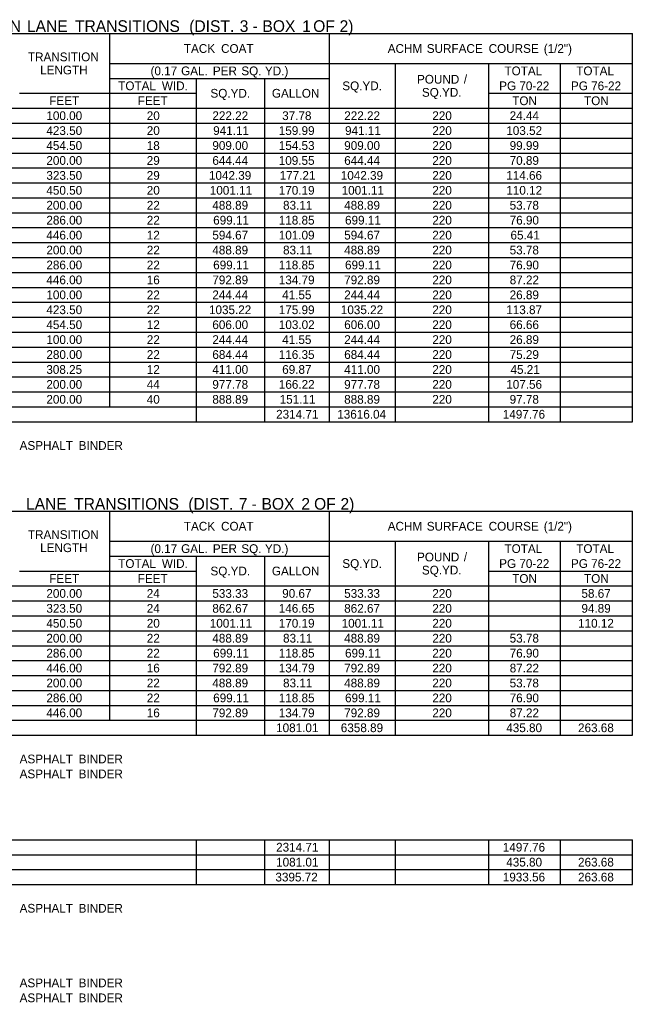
# Model space of a CAD drawing. Extents: x 544478 to 1930787, y -1948294 to 596640.
# Drawn here: x 548715 to 549135, y -1946843 to -1946169 of the extents above; entities that cross this region are included whole.
import ezdxf

# ---------------------------------------------------------------- set-up
doc = ezdxf.new("R2010")
doc.units = 0
doc.layers.add('Default', color=7, linetype='Continuous')

msp = doc.modelspace()

# ---------------------------------------------------------------- linework, layer by layer
at = {"layer": 'Default'}
for p, q in [((548361.91, -1946178.84), (549135.09, -1946178.84)), ((548361.91, -1946178.84), (549135.09, -1946178.84)), ((548776.78, -1946434.78), (548776.78, -1946178.84)), ((548927.41, -1946199.32), (548927.41, -1946178.84)), ((548927.41, -1946445.02), (548927.41, -1946178.84)), ((549135.09, -1946445.02), (549135.09, -1946178.84)), ((548776.78, -1946199.32), (549135.09, -1946199.32)), ((548927.41, -1946199.32), (549036.61, -1946199.32)), ((548972.75, -1946445.02), (548972.75, -1946199.32)), ((549036.61, -1946445.02), (549036.61, -1946199.32)), ((549085.85, -1946445.02), (549085.85, -1946199.32)), ((548776.78, -1946209.55), (548927.41, -1946209.55)), ((548836.25, -1946445.02), (548836.25, -1946209.55)), ((548883.05, -1946445.02), (548883.05, -1946209.55)), ((548714.86, -1946219.79), (548776.78, -1946219.79)), ((548714.86, -1946219.79), (548836.25, -1946219.79)), ((548836.25, -1946230.03), (548836.25, -1946219.79)), ((549036.61, -1946219.79), (549135.09, -1946219.79)), ((548361.91, -1946230.03), (549135.09, -1946230.03)), ((548836.25, -1946230.03), (548883.05, -1946230.03)), ((548883.05, -1946230.03), (549135.09, -1946230.03)), ((548577.88, -1946240.27), (549135.09, -1946240.27)), ((548577.88, -1946250.5), (549135.09, -1946250.5)), ((548361.91, -1946260.74), (549135.09, -1946260.74)), ((548577.88, -1946270.98), (549135.09, -1946270.98)), ((548577.88, -1946281.22), (549135.09, -1946281.22)), ((548361.91, -1946291.45), (549036.61, -1946291.45)), ((548714.86, -1946291.45), (548836.25, -1946291.45)), ((548836.25, -1946291.45), (549135.09, -1946291.45)), ((549036.61, -1946291.45), (549085.85, -1946291.45)), ((548577.88, -1946301.69), (549135.09, -1946301.69)), ((548577.88, -1946311.93), (549135.09, -1946311.93)), ((548361.91, -1946322.17), (549135.09, -1946322.17)), ((548577.88, -1946332.4), (549135.09, -1946332.4)), ((548577.88, -1946342.64), (549135.09, -1946342.64)), ((548361.91, -1946352.88), (549036.61, -1946352.88)), ((548714.86, -1946352.88), (548836.25, -1946352.88)), ((548836.25, -1946352.88), (549135.09, -1946352.88)), ((548577.88, -1946363.12), (549135.09, -1946363.12)), ((548577.88, -1946373.35), (549135.09, -1946373.35)), ((548361.91, -1946383.59), (549135.09, -1946383.59)), ((548577.88, -1946393.83), (549135.09, -1946393.83)), ((548577.88, -1946404.07), (549135.09, -1946404.07)), ((548361.91, -1946414.3), (549135.09, -1946414.3)), ((548577.88, -1946414.3), (549135.09, -1946414.3)), ((548524.25, -1946424.54), (549135.09, -1946424.54)), ((549036.61, -1946424.54), (549135.09, -1946424.54)), ((548361.91, -1946434.78), (549135.09, -1946434.78)), ((549036.61, -1946434.78), (549085.85, -1946434.78)), ((549085.85, -1946434.78), (549135.09, -1946434.78)), ((548361.91, -1946445.02), (549135.09, -1946445.02)), ((548361.91, -1946506.44), (549135.09, -1946506.44)), ((548361.91, -1946506.44), (549135.09, -1946506.44)), ((548776.78, -1946649.77), (548776.78, -1946506.44)), ((548927.41, -1946526.92), (548927.41, -1946506.44)), ((548927.41, -1946660), (548927.41, -1946506.44)), ((549135.09, -1946660), (549135.09, -1946506.44)), ((548776.78, -1946526.92), (549135.09, -1946526.92)), ((548927.41, -1946526.92), (549036.61, -1946526.92)), ((548972.75, -1946660), (548972.75, -1946526.92)), ((549036.61, -1946660), (549036.61, -1946526.92)), ((549085.85, -1946660), (549085.85, -1946526.92)), ((548776.78, -1946537.15), (548927.41, -1946537.15)), ((548836.25, -1946660), (548836.25, -1946537.15)), ((548883.05, -1946660), (548883.05, -1946537.15)), ((548714.86, -1946547.39), (548776.78, -1946547.39)), ((548714.86, -1946547.39), (548836.25, -1946547.39)), ((548836.25, -1946557.63), (548836.25, -1946547.39)), ((549036.61, -1946547.39), (549135.09, -1946547.39)), ((548361.91, -1946557.63), (549135.09, -1946557.63)), ((548836.25, -1946557.63), (548883.05, -1946557.63)), ((548883.05, -1946557.63), (549135.09, -1946557.63)), ((548577.88, -1946567.87), (549135.09, -1946567.87)), ((548577.88, -1946578.1), (548836.25, -1946578.1)), ((548577.88, -1946578.1), (548776.78, -1946578.1)), ((548776.78, -1946578.1), (549135.09, -1946578.1)), ((548361.91, -1946588.34), (549135.09, -1946588.34)), ((548577.88, -1946598.58), (549135.09, -1946598.58)), ((548577.88, -1946608.82), (548836.25, -1946608.82)), ((548577.88, -1946608.82), (548776.78, -1946608.82)), ((548776.78, -1946608.82), (549135.09, -1946608.82)), ((548361.91, -1946619.05), (549135.09, -1946619.05)), ((548577.88, -1946629.29), (549135.09, -1946629.29)), ((548577.88, -1946639.53), (548836.25, -1946639.53)), ((548577.88, -1946639.53), (548776.78, -1946639.53)), ((548776.78, -1946639.53), (549135.09, -1946639.53)), ((548361.91, -1946649.77), (549135.09, -1946649.77)), ((548361.91, -1946660), (549135.09, -1946660)), ((548361.91, -1946731.67), (549135.09, -1946731.67)), ((548361.91, -1946731.67), (549135.09, -1946731.67)), ((548836.25, -1946762.38), (548836.25, -1946731.67)), ((548883.05, -1946762.38), (548883.05, -1946731.67)), ((548927.41, -1946762.38), (548927.41, -1946731.67)), ((548972.75, -1946762.38), (548972.75, -1946731.67)), ((549036.61, -1946762.38), (549036.61, -1946731.67)), ((549085.85, -1946762.38), (549085.85, -1946731.67)), ((549135.09, -1946762.38), (549135.09, -1946731.67)), ((548361.91, -1946741.9), (549135.09, -1946741.9)), ((548361.91, -1946752.14), (549135.09, -1946752.14)), ((548361.91, -1946762.38), (549135.09, -1946762.38))]:
    msp.add_line(p, q, dxfattribs=at)

# ---------------------------------------------------------------- texts
for s, height, p in [(' MAIN', 8, (548686.12, -1946177.72)), (' LANE', 8, (548716.88, -1946177.72)), (' TRANSITIONS', 8, (548749.87, -1946177.72)), (' (DIST.', 8, (548828.19, -1946177.72)), (' 3', 8, (548862.81, -1946177.72)), (' -', 8, (548871.65, -1946177.72)), (' BOX', 8, (548878.39, -1946177.72)), (' 1', 8, (548905.71, -1946177.72)), (' OF', 8, (548913.21, -1946177.72)), (' 2)', 8, (548931.32, -1946177.72)), ('TACK', 6, (548827.5, -1946192.08)), (' COAT', 6, (548850.78, -1946192.08)), ('ACHM', 6, (548967.32, -1946192.08)), (' SURFACE', 6, (548991.87, -1946192.08)), (' COURSE', 6, (549034.31, -1946192.08)), (' (1/2")', 6, (549072.09, -1946192.08)), ('TRANSITION', 6, (548720.54, -1946197.82)), ('LENGTH', 6, (548728.91, -1946206.82)), ('(0.17', 6, (548804.65, -1946207.43)), (' GAL.', 6, (548823.38, -1946207.43)), (' PER', 6, (548845.16, -1946207.43)), (' SQ.', 6, (548864.68, -1946207.43)), (' YD.)', 6, (548880.88, -1946207.43)), ('TOTAL', 6, (549047.39, -1946207.43)), ('TOTAL', 6, (549096.62, -1946207.43)), ('POUND', 6, (548987.42, -1946213.17)), (' /', 6, (549017.28, -1946213.17)), ('TOTAL', 6, (548782.48, -1946217.67)), (' WID.', 6, (548810.17, -1946217.67)), ('SQ.YD.', 6, (548936.16, -1946217.67)), ('SQ.YD.', 6, (548990.76, -1946222.17)), ('PG', 6, (549043.76, -1946217.67)), (' 70-22', 6, (549055.37, -1946217.67)), ('PG', 6, (549093, -1946217.67)), (' 76-22', 6, (549104.6, -1946217.67)), ('FEET', 6, (548735.19, -1946227.91)), ('FEET', 6, (548795.88, -1946227.91)), ('SQ.YD.', 6, (548845.73, -1946222.79)), ('GALLON', 6, (548887.87, -1946222.79)), ('TON', 6, (549052.72, -1946227.91)), ('TON', 6, (549101.96, -1946227.91)), ('100.00', 6, (548733.21, -1946238.15)), ('20', 6, (548802.05, -1946238.15)), ('222.22', 6, (548847.06, -1946238.15)), ('37.78', 6, (548894.93, -1946238.15)), ('222.22', 6, (548937.49, -1946238.15)), ('220', 6, (548997.89, -1946238.15)), ('24.44', 6, (549050.95, -1946238.15)), ('423.50', 6, (548733.21, -1946248.38)), ('20', 6, (548802.05, -1946248.38)), ('941.11', 6, (548847.61, -1946248.38)), ('159.99', 6, (548892.6, -1946248.38)), ('941.11', 6, (548938.04, -1946248.38)), ('220', 6, (548997.89, -1946248.38)), ('103.52', 6, (549048.64, -1946248.38)), ('454.50', 6, (548733.21, -1946258.62)), ('18', 6, (548802.04, -1946258.62)), ('909.00', 6, (548847.04, -1946258.62)), ('154.53', 6, (548892.61, -1946258.62)), ('909.00', 6, (548937.47, -1946258.62)), ('220', 6, (548997.89, -1946258.62)), ('99.99', 6, (549050.93, -1946258.62)), ('200.00', 6, (548733.21, -1946268.86)), ('29', 6, (548802.04, -1946268.86)), ('644.44', 6, (548847.04, -1946268.86)), ('109.55', 6, (548892.58, -1946268.86)), ('644.44', 6, (548937.47, -1946268.86)), ('220', 6, (548997.89, -1946268.86)), ('70.89', 6, (549050.93, -1946268.86)), ('323.50', 6, (548733.21, -1946279.1)), ('29', 6, (548802.04, -1946279.1)), ('1042.39', 6, (548844.69, -1946279.1)), ('177.21', 6, (548893.19, -1946279.1)), ('1042.39', 6, (548935.12, -1946279.1)), ('220', 6, (548997.89, -1946279.1)), ('114.66', 6, (549048.61, -1946279.1)), ('450.50', 6, (548733.21, -1946289.33)), ('20', 6, (548802.05, -1946289.33)), ('1001.11', 6, (548845.28, -1946289.33)), ('170.19', 6, (548892.6, -1946289.33)), ('1001.11', 6, (548935.71, -1946289.33)), ('220', 6, (548997.89, -1946289.33)), ('110.12', 6, (549048.64, -1946289.33)), ('200.00', 6, (548733.21, -1946299.57)), ('22', 6, (548802.07, -1946299.57)), ('488.89', 6, (548847.02, -1946299.57)), ('83.11', 6, (548895.52, -1946299.57)), ('488.89', 6, (548937.45, -1946299.57)), ('220', 6, (548997.89, -1946299.57)), ('53.78', 6, (549050.93, -1946299.57)), ('286.00', 6, (548733.21, -1946309.81)), ('22', 6, (548802.07, -1946309.81)), ('699.11', 6, (548847.61, -1946309.81)), ('118.85', 6, (548892.58, -1946309.81)), ('699.11', 6, (548938.04, -1946309.81)), ('220', 6, (548997.89, -1946309.81)), ('76.90', 6, (549050.95, -1946309.81)), ('446.00', 6, (548733.21, -1946320.05)), ('12', 6, (548802.07, -1946320.05)), ('594.67', 6, (548847.03, -1946320.05)), ('101.09', 6, (548892.6, -1946320.05)), ('594.67', 6, (548937.46, -1946320.05)), ('220', 6, (548997.89, -1946320.05)), ('65.41', 6, (549051.52, -1946320.05)), ('200.00', 6, (548733.21, -1946330.28)), ('22', 6, (548802.07, -1946330.28)), ('488.89', 6, (548847.02, -1946330.28)), ('83.11', 6, (548895.52, -1946330.28)), ('488.89', 6, (548937.45, -1946330.28)), ('220', 6, (548997.89, -1946330.28)), ('53.78', 6, (549050.93, -1946330.28)), ('286.00', 6, (548733.21, -1946340.52)), ('22', 6, (548802.07, -1946340.52)), ('699.11', 6, (548847.61, -1946340.52)), ('118.85', 6, (548892.58, -1946340.52)), ('699.11', 6, (548938.04, -1946340.52)), ('220', 6, (548997.89, -1946340.52)), ('76.90', 6, (549050.95, -1946340.52)), ('446.00', 6, (548733.21, -1946350.76)), ('16', 6, (548802.04, -1946350.76)), ('792.89', 6, (548847.02, -1946350.76)), ('134.79', 6, (548892.6, -1946350.76)), ('792.89', 6, (548937.45, -1946350.76)), ('220', 6, (548997.89, -1946350.76)), ('87.22', 6, (549050.97, -1946350.76)), ('100.00', 6, (548733.21, -1946361)), ('22', 6, (548802.07, -1946361)), ('244.44', 6, (548847.04, -1946361)), ('41.55', 6, (548894.91, -1946361)), ('244.44', 6, (548937.47, -1946361)), ('220', 6, (548997.89, -1946361)), ('26.89', 6, (549050.93, -1946361)), ('423.50', 6, (548733.21, -1946371.23)), ('22', 6, (548802.07, -1946371.23)), ('1035.22', 6, (548844.73, -1946371.23)), ('175.99', 6, (548892.6, -1946371.23)), ('1035.22', 6, (548935.16, -1946371.23)), ('220', 6, (548997.89, -1946371.23)), ('113.87', 6, (549048.61, -1946371.23)), ('454.50', 6, (548733.21, -1946381.47)), ('12', 6, (548802.07, -1946381.47)), ('606.00', 6, (548847.04, -1946381.47)), ('103.02', 6, (548892.64, -1946381.47)), ('606.00', 6, (548937.47, -1946381.47)), ('220', 6, (548997.89, -1946381.47)), ('66.66', 6, (549050.94, -1946381.47)), ('100.00', 6, (548733.21, -1946391.71)), ('22', 6, (548802.07, -1946391.71)), ('244.44', 6, (548847.04, -1946391.71)), ('41.55', 6, (548894.91, -1946391.71)), ('244.44', 6, (548937.47, -1946391.71)), ('220', 6, (548997.89, -1946391.71)), ('26.89', 6, (549050.93, -1946391.71)), ('280.00', 6, (548733.21, -1946401.95)), ('22', 6, (548802.07, -1946401.95)), ('684.44', 6, (548847.04, -1946401.95)), ('116.35', 6, (548892.58, -1946401.95)), ('684.44', 6, (548937.47, -1946401.95)), ('220', 6, (548997.89, -1946401.95)), ('75.29', 6, (549050.93, -1946401.95)), ('308.25', 6, (548733.17, -1946412.18)), ('12', 6, (548802.07, -1946412.18)), ('411.00', 6, (548847.04, -1946412.18)), ('69.87', 6, (548894.94, -1946412.18)), ('411.00', 6, (548937.47, -1946412.18)), ('220', 6, (548997.89, -1946412.18)), ('45.21', 6, (549051.52, -1946412.18)), ('200.00', 6, (548733.21, -1946422.42)), ('44', 6, (548802.06, -1946422.42)), ('977.78', 6, (548847.02, -1946422.42)), ('166.22', 6, (548892.64, -1946422.42)), ('977.78', 6, (548937.45, -1946422.42)), ('220', 6, (548997.89, -1946422.42)), ('107.56', 6, (549048.61, -1946422.42)), ('200.00', 6, (548733.21, -1946432.66)), ('40', 6, (548802.05, -1946432.66)), ('888.89', 6, (548847.02, -1946432.66)), ('151.11', 6, (548893.19, -1946432.66)), ('888.89', 6, (548937.45, -1946432.66)), ('220', 6, (548997.89, -1946432.66)), ('97.78', 6, (549050.93, -1946432.66)), ('2314.71', 6, (548890.77, -1946442.9)), ('13616.04', 6, (548932.7, -1946442.9)), ('1497.76', 6, (549046.24, -1946442.9)), ('  ASPHALT', 6, (548710.4, -1946464.29)), (' BINDER', 6, (548753.1, -1946464.29)), (' LANE', 8, (548716.27, -1946505.32)), (' TRANSITIONS', 8, (548749.25, -1946505.32)), (' (DIST.', 8, (548827.57, -1946505.32)), (' 7', 8, (548862.19, -1946505.32)), (' BOX', 8, (548877.76, -1946505.32)), (' 2', 8, (548905.08, -1946505.32)), (' OF', 8, (548913.83, -1946505.32)), (' 2)', 8, (548931.94, -1946505.32)), (' -', 8, (548871.02, -1946505.32)), ('TRANSITION', 6, (548720.54, -1946525.42)), ('TACK', 6, (548827.5, -1946519.68)), (' COAT', 6, (548850.78, -1946519.68)), ('ACHM', 6, (548967.32, -1946519.68)), (' SURFACE', 6, (548991.87, -1946519.68)), (' COURSE', 6, (549034.31, -1946519.68)), (' (1/2")', 6, (549072.09, -1946519.68)), ('LENGTH', 6, (548728.91, -1946534.42)), ('(0.17', 6, (548804.65, -1946535.03)), (' GAL.', 6, (548823.38, -1946535.03)), (' PER', 6, (548845.16, -1946535.03)), (' SQ.', 6, (548864.68, -1946535.03)), (' YD.)', 6, (548880.88, -1946535.03)), ('TOTAL', 6, (549047.39, -1946535.03)), ('TOTAL', 6, (549096.62, -1946535.03)), ('TOTAL', 6, (548782.48, -1946545.27)), (' WID.', 6, (548810.17, -1946545.27)), ('SQ.YD.', 6, (548936.16, -1946545.27)), ('POUND', 6, (548987.42, -1946540.77)), (' /', 6, (549017.28, -1946540.77)), ('PG', 6, (549043.76, -1946545.27)), (' 70-22', 6, (549055.37, -1946545.27)), ('PG', 6, (549093, -1946545.27)), (' 76-22', 6, (549104.6, -1946545.27)), ('SQ.YD.', 6, (548845.73, -1946550.39)), ('GALLON', 6, (548887.87, -1946550.39)), ('SQ.YD.', 6, (548990.76, -1946549.77)), ('FEET', 6, (548735.19, -1946555.51)), ('FEET', 6, (548795.88, -1946555.51)), ('TON', 6, (549052.72, -1946555.51)), ('TON', 6, (549101.96, -1946555.51)), ('200.00', 6, (548733.21, -1946565.75)), ('24', 6, (548802.06, -1946565.75)), ('533.33', 6, (548847.03, -1946565.75)), ('90.67', 6, (548894.94, -1946565.75)), ('533.33', 6, (548937.46, -1946565.75)), ('220', 6, (548997.89, -1946565.75)), ('58.67', 6, (549100.17, -1946565.75)), ('323.50', 6, (548733.21, -1946575.98)), ('24', 6, (548802.06, -1946575.98)), ('862.67', 6, (548847.03, -1946575.98)), ('146.65', 6, (548892.58, -1946575.98)), ('862.67', 6, (548937.46, -1946575.98)), ('220', 6, (548997.89, -1946575.98)), ('94.89', 6, (549100.17, -1946575.98)), ('450.50', 6, (548733.21, -1946586.22)), ('20', 6, (548802.05, -1946586.22)), ('1001.11', 6, (548845.28, -1946586.22)), ('170.19', 6, (548892.6, -1946586.22)), ('1001.11', 6, (548935.71, -1946586.22)), ('220', 6, (548997.89, -1946586.22)), ('110.12', 6, (549097.88, -1946586.22)), ('200.00', 6, (548733.21, -1946596.46)), ('22', 6, (548802.07, -1946596.46)), ('488.89', 6, (548847.02, -1946596.46)), ('83.11', 6, (548895.52, -1946596.46)), ('488.89', 6, (548937.45, -1946596.46)), ('220', 6, (548997.89, -1946596.46)), ('53.78', 6, (549050.93, -1946596.46)), ('286.00', 6, (548733.21, -1946606.7)), ('22', 6, (548802.07, -1946606.7)), ('699.11', 6, (548847.61, -1946606.7)), ('118.85', 6, (548892.58, -1946606.7)), ('699.11', 6, (548938.04, -1946606.7)), ('220', 6, (548997.89, -1946606.7)), ('76.90', 6, (549050.95, -1946606.7)), ('446.00', 6, (548733.21, -1946616.93)), ('16', 6, (548802.04, -1946616.93)), ('792.89', 6, (548847.02, -1946616.93)), ('134.79', 6, (548892.6, -1946616.93)), ('792.89', 6, (548937.45, -1946616.93)), ('220', 6, (548997.89, -1946616.93)), ('87.22', 6, (549050.97, -1946616.93)), ('200.00', 6, (548733.21, -1946627.17)), ('22', 6, (548802.07, -1946627.17)), ('488.89', 6, (548847.02, -1946627.17)), ('83.11', 6, (548895.52, -1946627.17)), ('488.89', 6, (548937.45, -1946627.17)), ('220', 6, (548997.89, -1946627.17)), ('53.78', 6, (549050.93, -1946627.17)), ('286.00', 6, (548733.21, -1946637.41)), ('22', 6, (548802.07, -1946637.41)), ('699.11', 6, (548847.61, -1946637.41)), ('118.85', 6, (548892.58, -1946637.41)), ('699.11', 6, (548938.04, -1946637.41)), ('220', 6, (548997.89, -1946637.41)), ('76.90', 6, (549050.95, -1946637.41)), ('446.00', 6, (548733.21, -1946647.65)), ('16', 6, (548802.04, -1946647.65)), ('792.89', 6, (548847.02, -1946647.65)), ('134.79', 6, (548892.6, -1946647.65)), ('792.89', 6, (548937.45, -1946647.65)), ('220', 6, (548997.89, -1946647.65)), ('87.22', 6, (549050.97, -1946647.65)), ('1081.01', 6, (548890.77, -1946657.88)), ('6358.89', 6, (548935.13, -1946657.88)), ('435.80', 6, (549048.62, -1946657.88)), ('263.68', 6, (549097.84, -1946657.88)), ('  ASPHALT', 6, (548710.4, -1946679.28)), (' BINDER', 6, (548753.1, -1946679.28)), ('  ASPHALT', 6, (548710.4, -1946689.52)), (' BINDER', 6, (548753.1, -1946689.52)), ('2314.71', 6, (548890.77, -1946739.78)), ('1497.76', 6, (549046.24, -1946739.78)), ('1081.01', 6, (548890.77, -1946750.02)), ('435.80', 6, (549048.62, -1946750.02)), ('263.68', 6, (549097.84, -1946750.02)), ('3395.72', 6, (548890.3, -1946760.26)), ('1933.56', 6, (549046.24, -1946760.26)), ('263.68', 6, (549097.84, -1946760.26)), ('  ASPHALT', 6, (548710.4, -1946781.65)), (' BINDER', 6, (548753.1, -1946781.65)), ('  ASPHALT', 6, (548710.4, -1946832.84)), (' BINDER', 6, (548753.1, -1946832.84)), ('  ASPHALT', 6, (548710.4, -1946843.08)), (' BINDER', 6, (548753.1, -1946843.08))]:
    msp.add_text(s, height=height, dxfattribs=at).set_placement(p)

doc.saveas('drawing.dxf')
